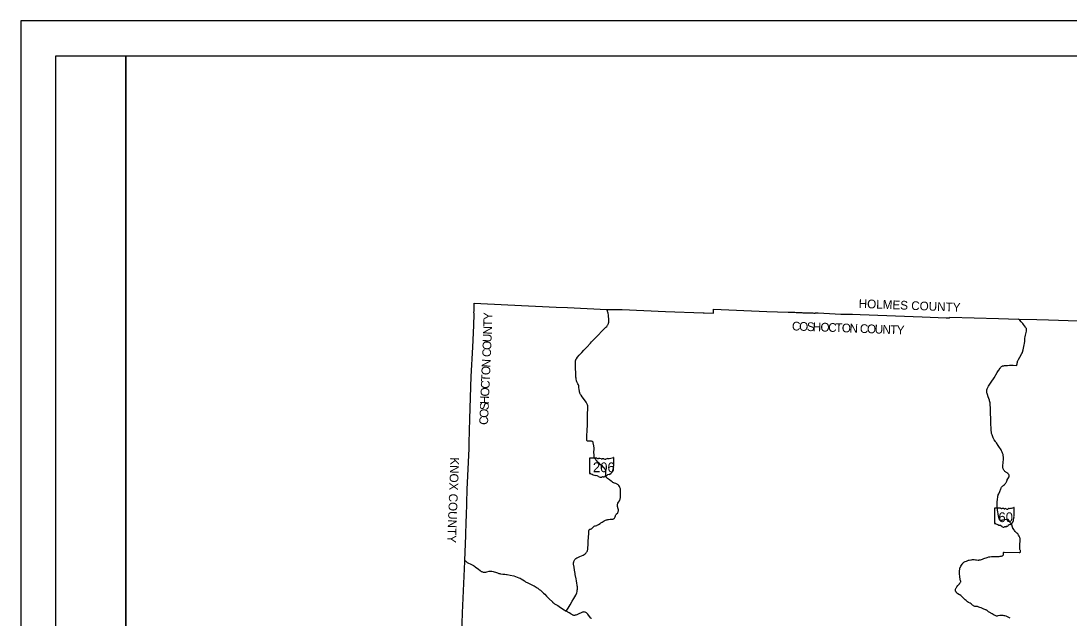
# Model space of a CAD drawing. Extents: x 2004415 to 2276415, y 751181 to 927181.
# Drawn here: x 2004415 to 2124487, y 858783 to 927181 of the extents above; entities that cross this region are included whole.
import ezdxf

# ---------------------------------------------------------------- set-up
doc = ezdxf.new("R2010")
doc.units = 0
for name, color, linetype in [('GM_X_County', 7, 'Continuous'), ('GM_X_County_Text', 7, 'Continuous'), ('GM_X_State_Location', 7, 'Continuous'), ('GM_X_State_Route', 7, 'Continuous'), ('GM_X_State_Shield', 7, 'Continuous'), ('SH_Border', 7, 'Continuous'), ('SH_Cut_Line', 7, 'Continuous')]:
    doc.layers.add(name, color=color, linetype=linetype)

msp = doc.modelspace()

# ---------------------------------------------------------------- linework, layer by layer
at = {"layer": 'GM_X_County'}
msp.add_lwpolyline([(2054895, 855723), (2054985, 859397), (2055260, 865250), (2055262, 865369), (2055375, 868236), (2055434, 869842), (2055436, 869891), (2055458, 870451), (2055528, 873511), (2055763, 878218), (2055757, 878860), (2055829, 881600), (2056002, 886440), (2056177, 889807), (2056314, 892278), (2056309, 892841), (2056319, 893081), (2056330, 893288), (2056336, 893469), (2056334, 893555), (2056318, 893677), (2056311, 893750), (2056312, 893777), (2056317, 893849), (2056325, 893939), (2056331, 894092), (2056334, 894166), (2056354, 894848), (2060194, 894658), (2065733, 894398), (2067044, 894350), (2071530, 894116), (2071597, 894123), (2071613, 894127), (2071629, 894129), (2071662, 894130), (2071728, 894128), (2071793, 894128), (2071907, 894132), (2071967, 894131), (2072076, 894132), (2072165, 894133), (2072229, 894134), (2072289, 894136), (2072356, 894136), (2072419, 894136), (2072511, 894135), (2072636, 894133), (2072760, 894131), (2072855, 894131), (2072933, 894131), (2072983, 894131), (2073056, 894131), (2073184, 894127), (2073228, 894125), (2073254, 894123), (2073277, 894122), (2073291, 894123), (2078246, 893887), (2082573, 893736), (2082680, 893741), (2083745, 893714), (2083760, 894177), (2089853, 893910), (2092311, 893824), (2092330, 893833), (2092354, 893838), (2092474, 893831), (2092606, 893825), (2092739, 893820), (2092877, 893816), (2092977, 893815), (2093060, 893814), (2093222, 893801), (2093313, 893798), (2093516, 893793), (2093635, 893787), (2093748, 893779), (2093892, 893769), (2094007, 893763), (2094089, 893758), (2094155, 893756), (2094237, 893753), (2094318, 893749), (2094383, 893748), (2094463, 893747), (2094512, 893746), (2094577, 893744), (2094642, 893741), (2094692, 893739), (2094774, 893736), (2094889, 893732), (2094970, 893730), (2095148, 893728), (2095240, 893725), (2095265, 893725), (2095332, 893722), (2095388, 893724), (2095407, 893725), (2095423, 893730), (2095440, 893741), (2095455, 893740), (2095734, 893742), (2098338, 893608), (2098370, 893608), (2098468, 893604), (2098516, 893603), (2098565, 893602), (2098663, 893601), (2098729, 893602), (2098768, 893602), (2098811, 893601), (2098842, 893600), (2098924, 893597), (2099032, 893594), (2099135, 893590), (2099228, 893585), (2099324, 893583), (2099412, 893583), (2099434, 893583), (2099500, 893584), (2099570, 893584), (2099629, 893585), (2099656, 893583), (2099662, 893582), (2099665, 893582), (2100553, 893564), (2107669, 893286), (2110409, 893179), (2110809, 893163), (2110813, 893230), (2110816, 893268), (2116419, 893104), (2118701, 893034), (2120795, 892965), (2122132, 892938), (2125547, 892838)], dxfattribs=at)
at = {"layer": 'GM_X_State_Route'}
for p, q in [((2117697, 887750), (2117708, 887750)), ((2116451, 887199), (2116470, 887231)), ((2111928, 862713), (2111935, 862722)), ((2066879, 859588), (2067019, 859807)), ((2067222, 859368), (2066879, 859588)), ((2067397, 859255), (2067222, 859368)), ((2067442, 859227), (2067397, 859255))]:
    msp.add_line(p, q, dxfattribs=at)
for points in [[(2069354, 883025), (2069354, 883041), (2069347, 883114), (2069339, 883166), (2069321, 883221), (2069298, 883275), (2069259, 883354), (2069164, 883498), (2068968, 883790), (2068721, 884126), (2068594, 884296), (2068520, 884405), (2068477, 884483), (2068443, 884556), (2068424, 884614), (2068412, 884663), (2068392, 884775), (2068366, 884979), (2068345, 885186), (2068330, 885293), (2068312, 885370), (2068271, 885484), (2068216, 885608), (2068153, 885746), (2068112, 885844), (2068075, 885953), (2068063, 885998), (2068032, 886152), (2068018, 886245), (2067998, 886389), (2067987, 886521), (2067978, 886628), (2067977, 886695), (2067970, 886873), (2067961, 887361), (2067946, 888065), (2067947, 888211), (2067956, 888280), (2067970, 888327), (2067995, 888383), (2068045, 888465), (2068193, 888660), (2068380, 888900), (2068540, 889086), (2068614, 889163), (2068661, 889210), (2068899, 889464), (2068956, 889522), (2069047, 889619), (2069241, 889826), (2069654, 890266), (2069793, 890414), (2070081, 890726), (2070570, 891242), (2070931, 891617), (2071225, 891904), (2071421, 892092), (2071518, 892189), (2071573, 892255), (2071614, 892314), (2071650, 892383), (2071678, 892453), (2071708, 892530), (2071732, 892594), (2071750, 892657), (2071760, 892715), (2071767, 892794), (2071767, 892872), (2071758, 892994), (2071751, 893088), (2071735, 893282), (2071712, 893465), (2071669, 893706), (2071643, 893833), (2071627, 893900), (2071609, 893972), (2071589, 894019), (2071569, 894061), (2071531, 894113)], [(2118488, 887722), (2118507, 887775), (2118526, 887889), (2118540, 887966), (2118565, 888080), (2118580, 888148), (2118601, 888204), (2118626, 888265), (2118705, 888416), (2118846, 888666), (2119084, 889098), (2119137, 889197), (2119166, 889261), (2119185, 889324), (2119202, 889389), (2119231, 889522), (2119354, 890094), (2119381, 890228), (2119395, 890331), (2119404, 890438), (2119421, 890729), (2119432, 890836), (2119456, 891009), (2119490, 891182), (2119601, 891634), (2119617, 891719), (2119623, 891784), (2119621, 891834), (2119616, 891870), (2119595, 891941), (2119555, 892022), (2119495, 892112), (2119369, 892275), (2119263, 892420), (2119178, 892529), (2119128, 892590), (2119012, 892715), (2118841, 892890), (2118757, 892977), (2118702, 893031)], [(2116470, 887231), (2116568, 887389), (2116618, 887463), (2116658, 887519), (2116718, 887578), (2116764, 887614), (2116810, 887638)], [(2116810, 887638), (2116850, 887655), (2116899, 887670), (2116949, 887682), (2117018, 887691), (2117096, 887698), (2117136, 887701), (2117229, 887709), (2117351, 887720), (2117442, 887731), (2117666, 887750), (2117697, 887750)], [(2117708, 887750), (2117792, 887751), (2118079, 887740), (2118488, 887722)], [(2117047, 875687), (2117027, 875713), (2116979, 875793), (2116943, 875868), (2116925, 875923), (2116916, 875984), (2116911, 876046), (2116920, 876203), (2116945, 876614), (2116963, 876983), (2116966, 877095), (2116962, 877234), (2116949, 877333), (2116922, 877502), (2116881, 877663), (2116829, 877802), (2116763, 877951), (2116716, 878040), (2116648, 878151), (2116528, 878330), (2116381, 878545), (2116162, 878859), (2116112, 878934), (2116054, 879015), (2115922, 879211), (2115844, 879337), (2115804, 879422), (2115753, 879540), (2115711, 879647), (2115667, 879778), (2115623, 879926), (2115604, 880007), (2115587, 880109), (2115574, 880204), (2115567, 880293), (2115557, 880479), (2115548, 880694), (2115543, 880831), (2115527, 881264), (2115517, 881653), (2115513, 881804), (2115503, 882076), (2115483, 882556), (2115473, 882913), (2115462, 883175), (2115454, 883304), (2115437, 883429), (2115418, 883551), (2115393, 883664), (2115367, 883748), (2115296, 883950), (2115231, 884133), (2115141, 884399), (2115101, 884508), (2115073, 884593), (2115059, 884656), (2115056, 884700), (2115053, 884773), (2115059, 884859), (2115076, 884942), (2115103, 885029), (2115147, 885118), (2115276, 885329), (2115564, 885785), (2115891, 886302), (2116258, 886894), (2116423, 887154), (2116451, 887199)], [(2069259, 879626), (2069285, 880303), (2069290, 880384), (2069303, 880792), (2069305, 881085), (2069316, 881624), (2069326, 882008), (2069335, 882269), (2069354, 882654), (2069358, 882807), (2069355, 882940), (2069354, 883025)], [(2069415, 867587), (2069441, 868010), (2069471, 868493), (2069480, 868699), (2069488, 868794), (2069504, 868850), (2069524, 868891), (2069556, 868928), (2069599, 868957), (2069659, 868980), (2069735, 869004), (2069775, 869020), (2069818, 869044), (2069873, 869090), (2069931, 869155), (2069996, 869223), (2070043, 869262), (2070101, 869302), (2070162, 869333), (2070238, 869361), (2070373, 869400), (2070444, 869426), (2070518, 869460), (2070599, 869509), (2070753, 869611), (2070855, 869680), (2070989, 869765), (2071110, 869836), (2071237, 869903), (2071391, 869980), (2071514, 870028), (2071574, 870047), (2071645, 870063), (2071737, 870076), (2071922, 870094), (2072139, 870112), (2072228, 870120), (2072293, 870136), (2072327, 870150), (2072360, 870176), (2072375, 870187), (2072402, 870215), (2072441, 870286), (2072478, 870387), (2072511, 870482), (2072533, 870540), (2072560, 870591), (2072587, 870632), (2072656, 870710), (2072779, 870850), (2072805, 870889), (2072834, 870948), (2072852, 871006), (2072862, 871057), (2072862, 871129), (2072853, 871191), (2072831, 871282), (2072768, 871545), (2072756, 871619), (2072749, 871689), (2072748, 871748), (2072757, 871811), (2072777, 871886), (2072805, 871960), (2072866, 872058), (2072991, 872226), (2073042, 872327), (2073065, 872404), (2073074, 872473), (2073082, 872550), (2073091, 872802), (2073104, 873214), (2073104, 873433), (2073098, 873517), (2073089, 873588), (2073064, 873668), (2073031, 873739), (2072975, 873851), (2072897, 873971), (2072832, 874043), (2072773, 874097), (2072719, 874133), (2072643, 874170), (2072548, 874204), (2072417, 874239), (2072353, 874258), (2072296, 874285), (2072230, 874322), (2072132, 874397), (2072022, 874481), (2071833, 874624), (2071733, 874690), (2071636, 874753), (2071592, 874784), (2071535, 874832), (2071497, 874881), (2071474, 874919), (2071458, 874962), (2071447, 875016), (2071429, 875154), (2071415, 875276), (2071411, 875367), (2071412, 875468), (2071409, 875584), (2071403, 875660), (2071387, 875726), (2071356, 875794), (2071309, 875865), (2071250, 875942), (2071191, 876006), (2071022, 876165), (2070782, 876377), (2070638, 876509), (2070537, 876609), (2070335, 876831), (2070274, 876902), (2070225, 876966), (2070187, 877017), (2070156, 877068), (2070117, 877140), (2070094, 877206), (2070078, 877267), (2070071, 877339), (2070068, 877432), (2070064, 877790), (2070066, 878137), (2070069, 878261), (2070066, 878334), (2070059, 878401), (2070039, 878527), (2069971, 878859), (2069954, 878919), (2069924, 878965), (2069888, 878996), (2069838, 879019), (2069778, 879030), (2069713, 879031), (2069561, 879030), (2069395, 879030), (2069341, 879034), (2069305, 879050), (2069282, 879065), (2069249, 879105), (2069240, 879126), (2069239, 879153), (2069241, 879253), (2069249, 879375), (2069259, 879626)], [(2117475, 874716), (2117549, 874833), (2117586, 874895), (2117608, 874961), (2117619, 875007), (2117621, 875051), (2117621, 875097), (2117609, 875166), (2117593, 875213), (2117566, 875267), (2117529, 875319), (2117496, 875355), (2117454, 875392), (2117399, 875426), (2117259, 875501), (2117192, 875543), (2117139, 875586), (2117083, 875640), (2117047, 875687)], [(2118780, 866300), (2118812, 866299), (2118850, 866304), (2118890, 866317), (2118925, 866346), (2118937, 866395), (2118927, 866454), (2118908, 866524), (2118887, 866572), (2118858, 866636), (2118842, 866676), (2118832, 866736), (2118837, 866818), (2118842, 866889), (2118855, 867054), (2118863, 867173), (2118866, 867260), (2118877, 867588), (2118885, 867774), (2118881, 867845), (2118875, 867893), (2118859, 867957), (2118833, 868022), (2118768, 868155), (2118709, 868271), (2118657, 868362), (2118602, 868422), (2118512, 868496), (2118422, 868569), (2118390, 868601), (2118348, 868651), (2118309, 868706), (2118253, 868800), (2118205, 868879), (2118056, 869068), (2118032, 869107), (2118017, 869150), (2118010, 869201), (2117990, 869321), (2117973, 869379), (2117936, 869454), (2117846, 869575), (2117755, 869703), (2117686, 869804), (2117568, 869992), (2117550, 870024), (2117511, 870061), (2117473, 870072), (2117415, 870073), (2117131, 870039), (2117059, 870028), (2116867, 869976), (2116771, 869953), (2116697, 869944), (2116634, 869953), (2116588, 869969), (2116552, 869992), (2116525, 870029), (2116504, 870079), (2116476, 870204), (2116423, 870439), (2116366, 870730), (2116328, 870940), (2116297, 871132), (2116279, 871258), (2116263, 871391), (2116250, 871527), (2116247, 871629), (2116250, 871746), (2116256, 871840), (2116272, 872004), (2116307, 872430), (2116318, 872607), (2116324, 872670), (2116330, 872725), (2116341, 872769), (2116355, 872819), (2116385, 872895), (2116435, 873021), (2116543, 873282), (2116664, 873570), (2116701, 873652), (2116729, 873707), (2116766, 873779), (2116799, 873825), (2116820, 873855), (2116863, 873901), (2116909, 873936), (2116962, 873968), (2117038, 874020), (2117073, 874047), (2117117, 874085), (2117139, 874110), (2117215, 874196), (2117260, 874268), (2117288, 874321), (2117352, 874479), (2117395, 874574)], [(2117395, 874574), (2117416, 874624), (2117475, 874716)], [(2067019, 859807), (2067093, 859923), (2067320, 860292), (2067563, 860697), (2067753, 861007), (2067884, 861221), (2067978, 861387), (2068023, 861494), (2068086, 861679), (2068120, 861829), (2068146, 861972), (2068158, 862100), (2068162, 862215), (2068160, 862293), (2068157, 862358), (2068147, 862454), (2068135, 862535), (2068093, 862790), (2068052, 863026), (2068008, 863284), (2067923, 863775), (2067906, 863881), (2067847, 864255), (2067785, 864622), (2067732, 864953), (2067729, 865061), (2067735, 865132), (2067747, 865201), (2067766, 865267), (2067793, 865338), (2067830, 865413), (2067875, 865483), (2067929, 865546), (2067999, 865607), (2068083, 865661), (2068231, 865736), (2068459, 865837), (2068834, 866001), (2068950, 866060), (2069042, 866121), (2069103, 866176), (2069173, 866254), (2069222, 866318), (2069268, 866400), (2069306, 866480), (2069331, 866557), (2069351, 866634), (2069373, 866847), (2069390, 867115), (2069415, 867587)], [(2112075, 862934), (2112075, 862970), (2112074, 863015), (2112070, 863049), (2112031, 863251), (2111983, 863488), (2111960, 863625), (2111941, 863784), (2111930, 863962), (2111928, 864078), (2111934, 864173), (2111957, 864366), (2111970, 864443), (2111993, 864523), (2112036, 864626), (2112098, 864734), (2112182, 864857), (2112247, 864951), (2112302, 865023), (2112338, 865069), (2112376, 865108), (2112415, 865143), (2112452, 865170), (2112516, 865210), (2112596, 865253), (2112726, 865313), (2112806, 865347), (2112900, 865383), (2112971, 865405), (2113051, 865425), (2113234, 865455), (2113308, 865463), (2113446, 865478), (2113552, 865479), (2113633, 865473), (2113774, 865452), (2113884, 865444), (2114085, 865431), (2114146, 865431), (2114184, 865433), (2114242, 865443), (2114339, 865467), (2114559, 865535), (2114735, 865594), (2115095, 865716), (2115281, 865776), (2115395, 865800), (2115618, 865830), (2115744, 865842), (2115836, 865849), (2115943, 865841), (2116057, 865826), (2116143, 865821), (2116233, 865819), (2116305, 865822), (2116396, 865830), (2116489, 865851), (2116597, 865868), (2116740, 865880), (2116823, 865893), (2116866, 865914), (2116919, 865958), (2116960, 866010), (2116981, 866069), (2116987, 866120), (2116975, 866187), (2116968, 866234), (2116977, 866274), (2116989, 866298), (2117012, 866317), (2117044, 866335), (2118780, 866300)], [(2055263, 865366), (2055289, 865353), (2055333, 865323), (2055459, 865224), (2055546, 865163), (2055620, 865123), (2055701, 865083), (2055886, 864995), (2056119, 864885), (2056190, 864846), (2056262, 864799), (2056368, 864719), (2056454, 864650), (2056817, 864364), (2057011, 864216), (2057138, 864130), (2057196, 864099), (2057272, 864068), (2057353, 864047), (2057412, 864038), (2057487, 864033), (2057586, 864038), (2057668, 864048), (2057802, 864077), (2058058, 864135), (2058170, 864153), (2058278, 864153), (2058370, 864140), (2058495, 864112), (2058646, 864068), (2058795, 864019), (2058991, 863951), (2059159, 863901), (2059275, 863873), (2059353, 863859), (2059633, 863824), (2059840, 863801), (2060024, 863774), (2060132, 863755), (2060459, 863692), (2060889, 863602), (2061086, 863549), (2061271, 863482), (2061468, 863405), (2061599, 863344), (2061720, 863274), (2061908, 863150), (2062085, 863027), (2062161, 862978), (2062219, 862942), (2062280, 862907), (2062403, 862844), (2062626, 862737), (2063088, 862529), (2063200, 862474), (2063323, 862407), (2063544, 862260), (2063627, 862199)], [(2063627, 862199), (2063802, 862070), (2063930, 861970), (2064139, 861777), (2064258, 861661)], [(2111969, 861434), (2111947, 861447), (2111739, 861569), (2111649, 861638), (2111588, 861699), (2111559, 861733), (2111541, 861766), (2111513, 861824), (2111495, 861879), (2111483, 861944), (2111483, 862009), (2111494, 862081), (2111517, 862157), (2111554, 862225), (2111593, 862286), (2111651, 862369), (2111761, 862508), (2111928, 862713)], [(2111935, 862722), (2111982, 862779), (2112022, 862833), (2112055, 862883), (2112075, 862934)], [(2064258, 861661), (2064281, 861640), (2064420, 861502), (2064626, 861291), (2064942, 860978), (2065295, 860624)], [(2117739, 858771), (2117511, 858875), (2117274, 858979), (2117139, 859023), (2117036, 859046), (2116923, 859062), (2116752, 859071), (2116636, 859071), (2116566, 859064), (2116327, 859021), (2116238, 859011), (2116170, 859014), (2116098, 859031), (2116011, 859064), (2115910, 859113), (2115790, 859186), (2115672, 859265), (2115611, 859303), (2115540, 859344), (2115476, 859383), (2115345, 859456), (2115268, 859507), (2115178, 859576), (2115103, 859644), (2115048, 859683), (2114995, 859705), (2114917, 859728), (2114840, 859752), (2114741, 859797), (2114635, 859849), (2114428, 859946), (2114280, 860006), (2114160, 860045), (2114074, 860073), (2113983, 860087), (2113905, 860093), (2113774, 860106), (2113678, 860120), (2113606, 860144), (2113543, 860179), (2113501, 860217), (2113440, 860276), (2113366, 860335), (2113283, 860394), (2113151, 860474), (2112980, 860573), (2112865, 860649), (2112750, 860735), (2112694, 860778), (2112596, 860861), (2112471, 860973), (2112358, 861085), (2112285, 861160), (2112200, 861259), (2112143, 861320), (2112075, 861370), (2111969, 861434)], [(2065295, 860624), (2065307, 860613), (2065407, 860524), (2065468, 860478), (2065558, 860417), (2065903, 860205), (2066245, 859980), (2066654, 859724), (2066879, 859588)], [(2067682, 859105), (2067644, 859115), (2067587, 859140), (2067534, 859170), (2067442, 859227)], [(2067997, 859122), (2067910, 859097), (2067831, 859086), (2067751, 859091), (2067682, 859105)], [(2068733, 859453), (2068582, 859386), (2068316, 859266), (2068084, 859157), (2068002, 859123), (2067997, 859122)], [(2069342, 859242), (2069298, 859294), (2069249, 859347), (2069190, 859392), (2069120, 859428), (2069066, 859451), (2068996, 859469), (2068906, 859476), (2068820, 859473), (2068733, 859453)], [(2069671, 858825), (2069602, 858904), (2069557, 858968), (2069369, 859210), (2069342, 859242)], [(2069791, 858721), (2069755, 858742), (2069718, 858775), (2069674, 858821), (2069671, 858825)]]:
    msp.add_lwpolyline(points, dxfattribs=at)
at = {"layer": 'GM_X_State_Shield'}
for p, q in [((2069538, 877070), (2069538, 875369)), ((2070386, 877100), (2069566, 877100)), ((2072340, 876252), (2072340, 877142)), ((2072340, 876252), (2072340, 876252)), ((2115961, 871351), (2115961, 869650)), ((2116640, 871381), (2115984, 871381)), ((2118203, 870533), (2118203, 871423)), ((2118203, 870533), (2118203, 870533))]:
    msp.add_line(p, q, dxfattribs=at)
for centre, radius, start, end in [((2115987, 871355), 26, 98.1301, 188.1301), ((2116796, 871578), 252, 231.61951, 271.11188), ((2116880, 870426), 904, 80.48669, 94.98827), ((2117085, 871364), 72.7, 219.79206, 297.10237), ((2117192, 871167), 151, 54.46668, 119.14113), ((2117387, 871437), 182, 233.85621, 294.82819), ((2117708, 870861), 478, 97.34618, 120.76885), ((2117404, 873700), 2377, 275.84447, 288.90645), ((2118178, 871426), 25, 351.86209, 97.738), ((2118176, 870529), 26.7, 289.60381, 7.73413), ((2115987, 869646), 26.2, 171.95839, 258.30661), ((2115991, 869820), 200, 267.33899, 280.60386), ((2116032, 869552), 72.1, 29.74838, 93.27175), ((2116942, 871080), 1716, 240.41292, 257.1985), ((2116431, 868886), 537, 47.18416, 75.83597), ((2117376, 869485), 192, 282.87319, 323.27711), ((2117788, 869173), 326, 94.40312, 142.57675), ((2117538, 870047), 595, 292.30889, 8.98584), ((2118292, 870160), 169, 136.8065, 186.92959), ((2118197, 870468), 38.6, 107.94398, 210.33697), ((2117951, 870355), 232, 340.03296, 23.64957), ((2117011, 869544), 341, 230.70037, 286.29184), ((2117208, 868955), 280, 85.69512, 111.20995), ((2117233, 869416), 182, 268.77702, 315.54927), ((2117398, 869251), 51.1, 65.75173, 132.64842)]:
    msp.add_arc(centre, radius, start, end, dxfattribs=at)
for centre, major_axis, start_param, end_param in [((2069570, 877074), (32.5, 0), 1.7126934, 3.2834897), ((2070582, 877297), (315, 0), 4.042523, 4.731795), ((2070686, 876144), (1130, 0), 1.4047578, 1.6578581), ((2070943, 877083), (90.8, 0), 3.8360951, 5.1854146), ((2071076, 876886), (189, 0), 0.950623, 2.079405), ((2071320, 877156), (227, 0), 4.0815608, 5.1457227), ((2071721, 876580), (598, 0), 1.6990114, 2.1078141), ((2071342, 879419), (2971, 0), 4.8143942, 5.0423688), ((2072309, 877145), (31.2, 0), 6.1411519, 7.9890352), ((2069571, 875365), (32.7, 0), 3.00124, 4.5083009), ((2069576, 875539), (250, 0), 4.6659457, 4.8974612), ((2069627, 875271), (90.1, 0), 0.5192072, 1.6278991), ((2071509, 875766), (743, 0), 5.1017525, 6.4400178), ((2072452, 875879), (211, 0), 2.3877238, 3.2625369), ((2072333, 876186), (48.3, 0), 1.8839779, 3.6710726), ((2072026, 876074), (290, 0), 5.9346948, 6.6959481), ((2072307, 876248), (33.4, 0), 5.05454, 6.4181714), ((2070764, 876799), (2146, 0), 4.1959971, 4.4889607), ((2070125, 874605), (671, 0), 0.8235189, 1.3235874), ((2070851, 875263), (426, 0), 4.0264811, 4.9967352), ((2071097, 874674), (350, 0), 1.495662, 1.9409797), ((2071128, 875135), (227, 0), 4.6910439, 5.5073738), ((2071333, 874970), (63.9, 0), 1.1475842, 2.3151517), ((2071306, 875204), (240, 0), 4.9370686, 5.64225), ((2071822, 874892), (407, 0), 1.6476453, 2.4884337)]:
    msp.add_ellipse(centre, major_axis=major_axis, ratio=0.8, start_param=start_param, end_param=end_param, dxfattribs=at)
at = {"layer": 'SH_Border'}
for points in [[(2008415, 923181), (2016415, 923181), (2016415, 755181), (2008415, 755181)], [(2016415, 923181), (2272415, 923181), (2272415, 755181), (2016415, 755181)]]:
    msp.add_lwpolyline(points, close=True, dxfattribs=at)
at = {"layer": 'SH_Cut_Line'}
msp.add_lwpolyline([(2004415, 751181), (2276415, 751181), (2276415, 927181), (2004415, 927181)], close=True, dxfattribs=at)

# ---------------------------------------------------------------- texts
at = {"layer": 'GM_X_County_Text'}
for s, rotation, p in [('HOLMES COUNTY', 357.78436, (2100376, 894318)), ('Y', 89.57353, (2058405, 892914)), ('N', 87.87968, (2058356, 891250)), ('T', 88.80495, (2058389, 892152)), ('C', 356.90785, (2092721, 891750)), ('O', 357.75899, (2093550, 891706)), ('S', 357.89992, (2094436, 891671)), ('H', 357.942, (2095114, 891646)), ('O', 357.9493, (2095998, 891615)), ('C', 357.95077, (2096882, 891583)), ('T', 357.95019, (2097696, 891554)), ('O', 357.95098, (2098443, 891527)), ('N', 357.95091, (2099327, 891495)), ('C', 357.95077, (2100514, 891453)), ('O', 357.95091, (2101328, 891424)), ('U', 357.94873, (2102212, 891392)), ('N', 357.95098, (2103096, 891361)), ('T', 357.95085, (2103979, 891329)), ('Y', 357.95098, (2104727, 891302)), ('U', 87.63827, (2058319, 890362)), ('O', 87.55576, (2058281, 889477)), ('C', 87.53948, (2058246, 888663)), ('O', 87.53779, (2058157, 886593)), ('N', 87.53779, (2058195, 887476)), ('T', 87.53719, (2058125, 885845)), ('O', 87.53779, (2058052, 884148)), ('C', 87.53713, (2058090, 885032)), ('H', 87.53779, (2058014, 883265)), ('O', 87.53779, (2057947, 881704)), ('S', 87.53778, (2057985, 882588)), ('C', 87.53713, (2057912, 880891)), ('KNOX COUNTY', 267.8289, (2053620, 877211))]:
    msp.add_text(s, height=1000, rotation=rotation, dxfattribs=at).set_placement(p)
at = {"layer": 'GM_X_State_Location'}
for s, p in [('206', (2071292, 892173)), ('206', (2070834, 875823)), ('60', (2116317, 873134)), ('60', (2116457, 858878))]:
    msp.add_text(s, height=1, rotation=0.00001, dxfattribs=at).set_placement(p)
for s, p in [('s', (2071645, 892246)), ('r', (2071644, 892246)), ('s', (2071187, 875895)), ('r', (2071187, 875895)), ('s', (2116568, 873207)), ('r', (2116568, 873207)), ('s', (2116709, 858951)), ('r', (2116709, 858951))]:
    msp.add_text(s, height=1, dxfattribs=at).set_placement(p)
at = {"layer": 'GM_X_State_Shield'}
for s, p in [('206', (2069942, 875489)), ('60', (2116395, 869770))]:
    msp.add_text(s, height=1120.7, dxfattribs=at).set_placement(p)

doc.saveas('drawing.dxf')
